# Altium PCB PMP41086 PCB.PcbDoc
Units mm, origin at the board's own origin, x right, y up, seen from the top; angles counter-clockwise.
Board outline 36.5 x 25.7 mm, 2 copper layers (Top Layer, Bottom Layer), stack 1.575 mm thick; 40 components, 22 nets, 87 pads, 45 vias.
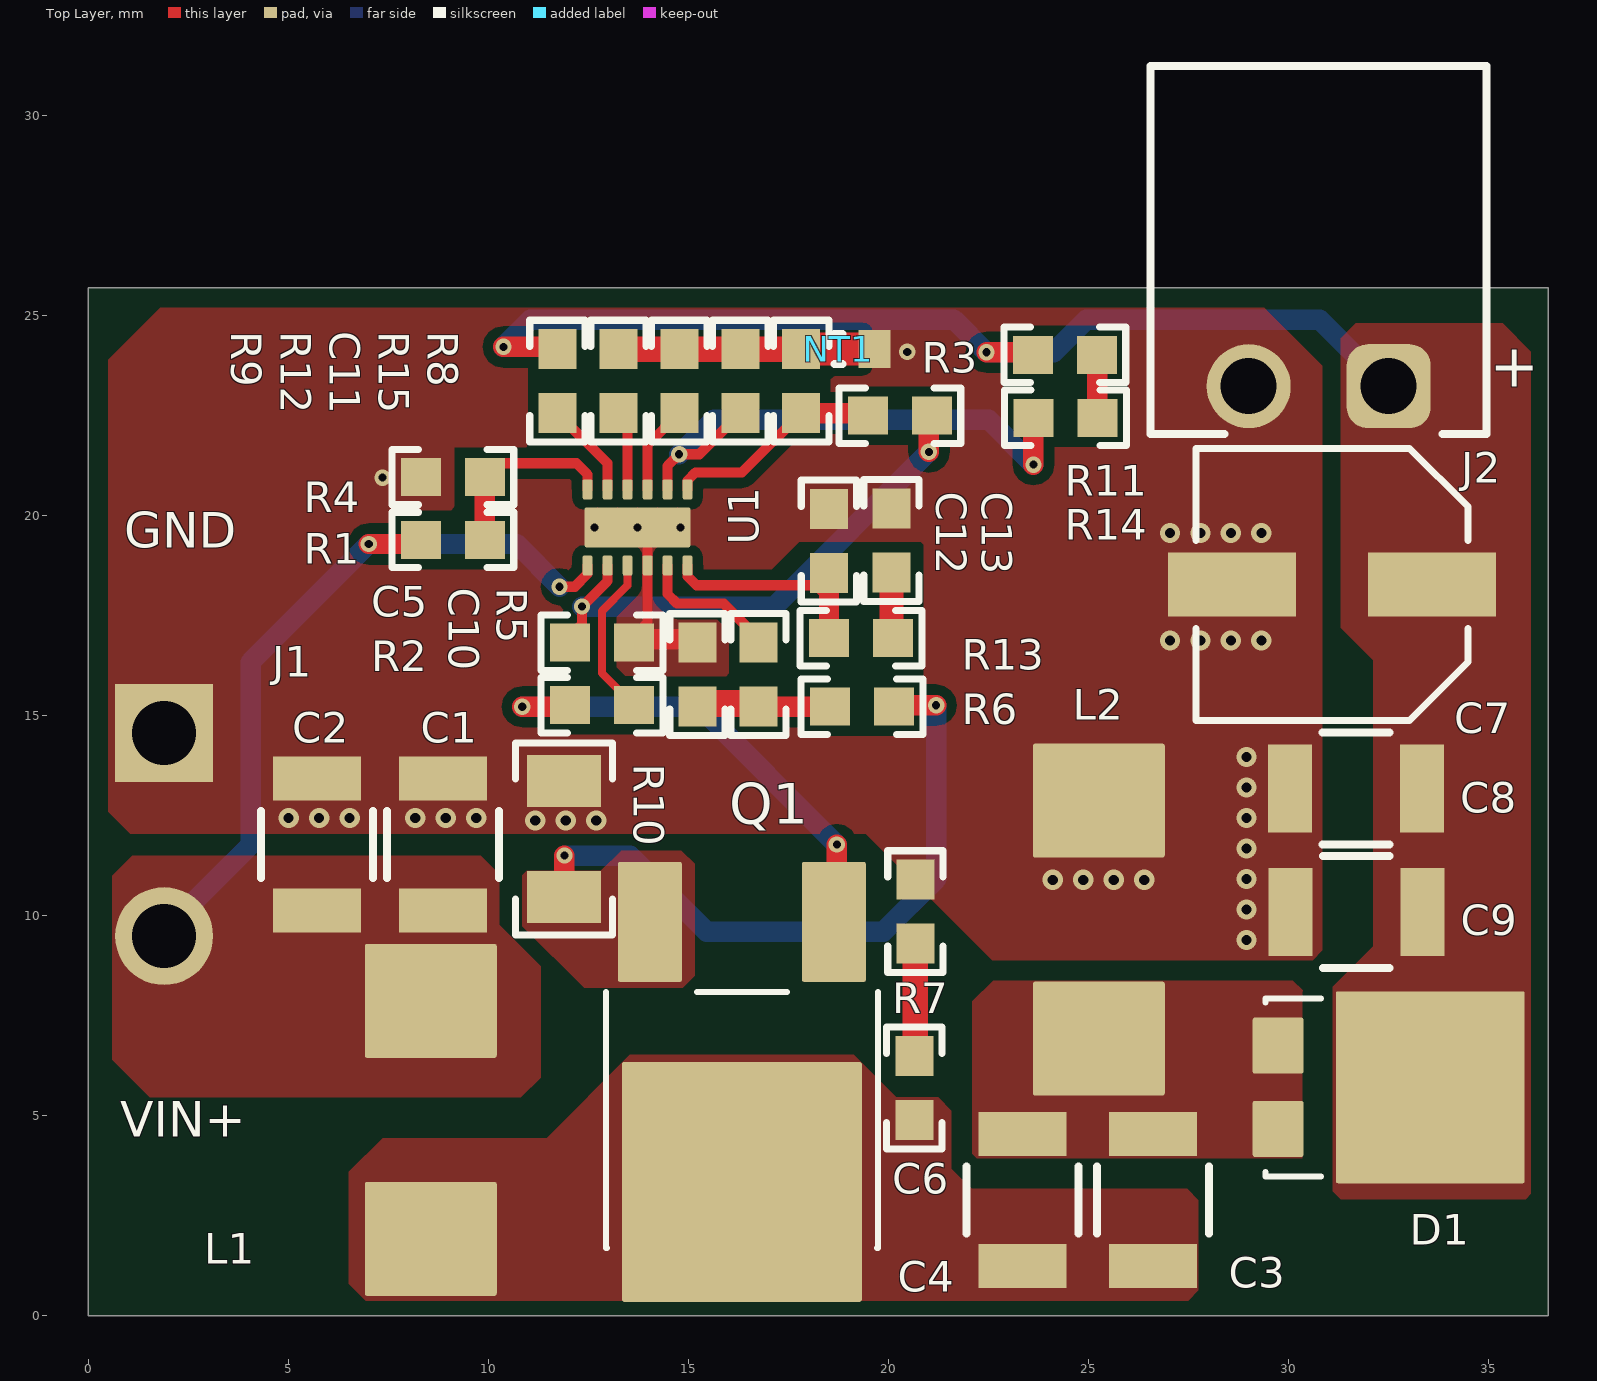
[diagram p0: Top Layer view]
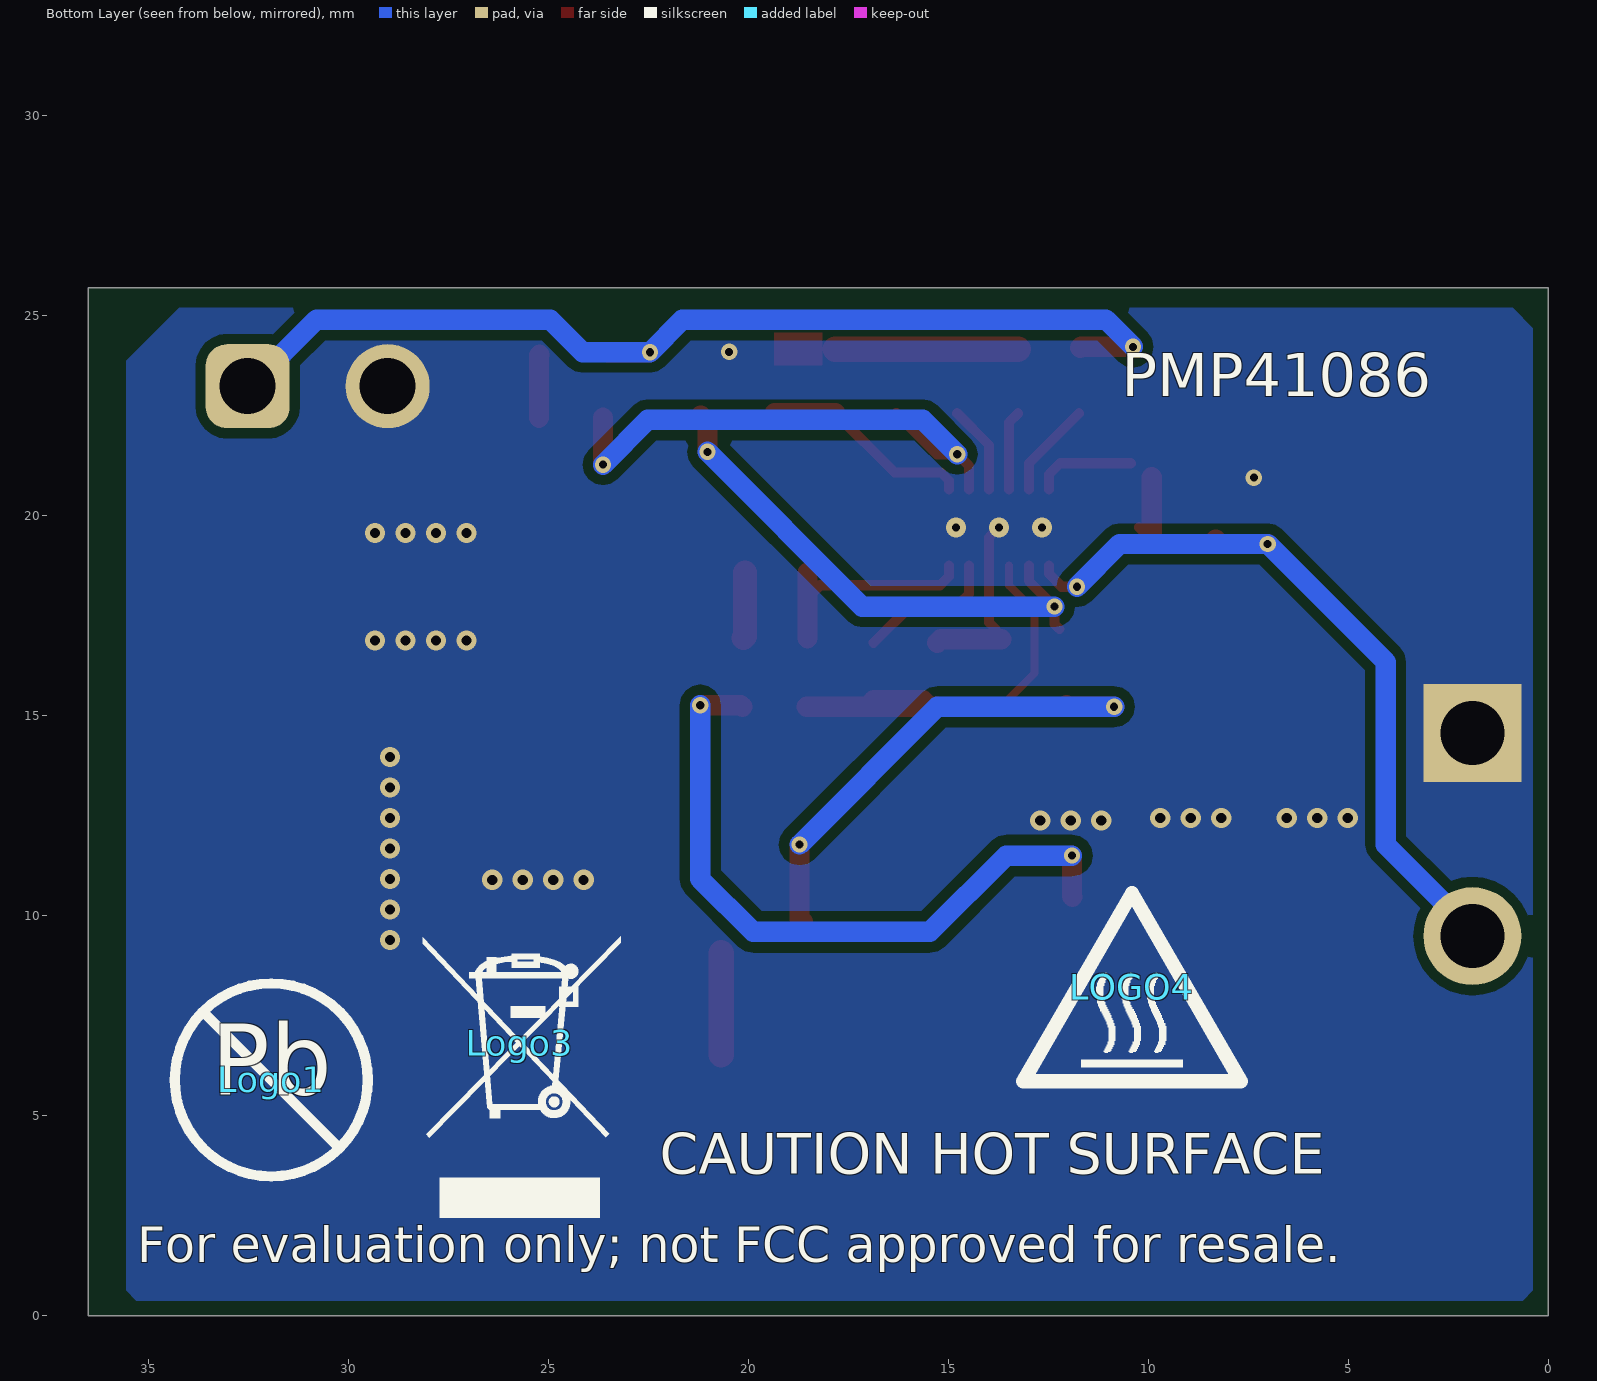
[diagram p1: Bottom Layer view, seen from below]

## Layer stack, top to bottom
Top Solder: solder mask 0.0102, Solder Resist, Dk 3.5
Top Layer: signal copper 0.0356
Dielectric1: core 1.5037, FR-4, Dk 4.8
Bottom Layer: signal copper 0.0356
Bottom Solder: solder mask 0.0102, Solder Resist, Dk 3.5

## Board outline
0,0 36.5,0 36.5,25.7 0,25.7

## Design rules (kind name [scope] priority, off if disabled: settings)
AcuteAngle [All] p1: minimum=4.50000000000000E+0001 checktracksonly=FALSE
AssemblyTestPointUsage [All] p1: valid=2
Clearance Clearance_BoardEdge_MountingHoles [OnCopper and InComponentClass('Mounting Holes') vs IsKeepOut] p1: gap=1.016 ignorepadtopadclearanceinfootprint=FALSE except(0: Arc-Hole Track-Hole SMDPad-Hole THPad-Hole Via-Hole Fill-Hole Poly-Hole Region-Hole Text-Hole)
Clearance Clearance_BoardEdge_Poly [OnCopper and InPoly vs IsKeepOut] p2: gap=0.635 ignorepadtopadclearanceinfootprint=FALSE except(0: Arc-Hole Track-Hole SMDPad-Hole THPad-Hole Via-Hole Fill-Hole Poly-Hole Region-Hole Text-Hole)
Clearance Clearance_BoardEdge [OnCopper and Not InComponentClass('Logo') and not InComponentClass('FiducialMark') and not InRegion(1000,500,4000,800) and Not IsKeepout vs IsKeepOut] p3: gap=0.127 ignorepadtopadclearanceinfootprint=FALSE except(0: Arc-Hole Track-Hole SMDPad-Hole THPad-Hole Via-Hole Fill-Hole Poly-Hole Region-Hole Text-Hole)
Clearance Clearance_Poly [InPolygon] p4: gap=0.254 ignorepadtopadclearanceinfootprint=FALSE
Clearance [All] p5: gap=0.2 ignorepadtopadclearanceinfootprint=FALSE
ComponentClearance ComponentClearance_Logo [All] p1: gap=0.254 collisioncheckmode=3 verticalgap=0.254 showdistances=TRUE
ComponentClearance ComponentClearance_ScrewToNut [(HasFootprint('NY PMS 440 0025 PH')) vs (HasFootprint('Keystone_1902C'))] p2: gap=0.127 collisioncheckmode=3 verticalgap=0.254 showdistances=FALSE
ComponentClearance ComponentClearance_MountingHoles [InComponentClass('Mounting Holes')] p3: gap=0.254 collisioncheckmode=3 verticalgap=2540 showdistances=FALSE
ComponentClearance ComponentClearance_SmallPassives [HasFootprint('0201*') or HasFootprint('0402*') or HasFootprint('0508') or HasFootprint('0603*') or HasFootprint('0612') or HasFootprint('0805*') or HasFootprint('0815*') or HasFootprint('0830*') or HasFootprint('1206*') or HasFootprint('1210*') or HasFootprint('1808*') or HasFootprint('1812*') or HasFootprint('1825*') or HasFootprint('2010*') or HasFootprint('2220*') or HasFootprint('2225*') or HasFootprint('2512*') or HasFootprint('2728*') or HasFootprint('3518*') vs HasFootprint('0201*') or HasFootprint('0402*') or HasFootprint('0508') or HasFootprint('0603*') or HasFootprint('0612') or HasFootprint('0805*') or HasFootprint('0815*') or HasFootprint('0830*') or HasFootprint('1206*') or HasFootprint('1210*') or HasFootprint('1808*') or HasFootprint('1812*') or HasFootprint('1825*') or HasFootprint('2010*') or HasFootprint('2220*') or HasFootprint('2225*') or HasFootprint('2512*') or HasFootprint('2728*') or HasFootprint('3518*')] p4: gap=0.254 collisioncheckmode=3 verticalgap=0.254 showdistances=FALSE
ComponentClearance ComponentClearance_THtoSMT [IsThruComponent vs IsSMTComponent] p5: gap=0.254 collisioncheckmode=3 verticalgap=2540 showdistances=FALSE
ComponentClearance ComponentClearance_THtoTH [IsThruComponent vs IsThruComponent] p6: gap=0.254 collisioncheckmode=3 verticalgap=2540 showdistances=FALSE
ComponentClearance [All] p7: gap=0.254 collisioncheckmode=3 verticalgap=0.254 showdistances=FALSE
DiffPairsRouting [All] p1: maxlimit=2.54 minlimit=0.254 mostfreqgap=0.254 toplayer_minwidth=0.381 toplayer_maxwidth=0.381 toplayer_prefwidth=0.381 bottomlayer_minwidth=0.381 bottomlayer_maxwidth=0.381 bottomlayer_prefwidth=0.381 maxuncoupledlength=25.4
FabricationTestPointUsage TestPointUsage [All] p1: valid=2 allowmultiple=FALSE
FabricationTestpoint Testpoint [All] p1: side=3 testpointundercomponent=TRUE minsize=1.016 maxsize=2.54 preferedsize=1.524 minholesize=0 maxholesize=1.016 preferedholesize=0.813 testpointgrid=0.025 allowsidetop=TRUE allowsidebottom=TRUE usegrid=TRUE gridtolerance=0
FanoutControl Fanout_LCC [IsLCC] p1: bgadir=Out bgaviamode=Centered fanoutstyle=Auto fanoutdirection=Alternating viagrid=0.025 // Fanout_LCC (Default Rule)
FanoutControl Fanout_BGA [IsBGA] p2: bgadir=Out bgaviamode=Centered fanoutstyle=Auto fanoutdirection=Alternating viagrid=0.025 // Fanout_BGA (Default Rule)
FanoutControl Fanout_Default [All] p4: bgadir=Out bgaviamode=Centered fanoutstyle=Auto fanoutdirection=Alternating viagrid=0.025 // Fanout_Default (Default Rule)
FanoutControl Fanout_Small [(CompPinCount < 5)] p5: bgadir=Out bgaviamode=Centered fanoutstyle=Auto fanoutdirection=OutThenIn viagrid=0.025 // Fanout_Small (Default Rule)
HoleSize [All] p1: absolutevalues=TRUE maxlimit=6.375 minlimit=0.152 maxpercent=80.000 minpercent=20.000
MinimumAnnularRing [All] p1: minimumring=0.076
MinimumSolderMaskSliver MinimumSolderMaskSliver_Logo [InComponentClass('Logo') vs InComponentClass('Logo')] p1: minsoldermaskwidth=0.018
MinimumSolderMaskSliver [All] p2: minsoldermaskwidth=0
PlaneConnect [All] p1: planeconnectstyle=Direct reliefexpansion=0.254 reliefentries=4 reliefconductorwidth=0.254 reliefairgap=0.254
PolygonConnect [All] p1: connectstyle=Direct reliefconductorwidth=0.254 reliefentries=4 polygonreliefangle="90 Angle" airgapwidth=0.254
RoutingCorners [All] p1: cornerstyle=45-Degree minsetback=0.254 maxsetback=2.54
RoutingVias [All] p1: holewidth=0.406 width=0.864 viastyle="Through Hole" minholewidth=0.198 minwidth=0.406 maxholewidth=1.016 maxwidth=1.651
SMDToCorner [All] p1: distance=0
SilkToBoardRegionClearance [Not ((IsComment or IsDesignator) And (Hide <> 'False')) and not InRegion(1000,500,4000,800)] p1:
SilkToSilkClearance [All] p1: silktosilkclearance=0
SilkToSolderMaskClearance SilkscreenOverComponentPads [IsPad] p1: minsilkscreentomaskgap=0 clearancetoexposedcopper=TRUE
SolderMaskExpansion [All] p1: expansion=0.076
Width [All] p1: maxlimit=2.54 minlimit=0.152 preferedwidth=0.254 checkconnectedcopper=TRUE
14 further rules are at their usual default settings.

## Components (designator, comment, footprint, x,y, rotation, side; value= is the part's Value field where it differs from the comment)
C1 "UMK325AB7106KMHT" 1210_280 8.875,11.784 r90 top value=10uF
C2 "UMK325AB7106KMHT" 1210_280 5.725,11.78 r90 top value=10uF
C3 "CGA6P3X7R1H475K250AB" 1210_280 26.616,2.9 r270 top value=4.7uF
C4 "CGA6P3X7R1H475K250AB" 1210_280 23.36,2.896 r270 top value=4.7uF
C5 "GCM188R71E105KA64D" 0603 12.842,16.828 r180 top value=1uF
C6 "GCM1885C2A221JA16D" 0603 20.653,5.698 r90 top value=220pF
C7 "EEE-FK1V101XP" SM_RADIAL_D8 31.094,18.288 r180 top value=100uF
C8 "UMK325AB7106KMHT" 1210_280 31.691,13.184 r180 top value=10uF
C9 "UMK325AB7106KMHT" 1210_280 31.702,10.092 r180 top value=10uF
C10 "CGA3E2NP01H101J080AA" 0603 15.23,16.028 r90 top value=100pF
C11 "CGA3E2X7R1E104K080AA" 0603 14.777,23.367 r90 top value=0.1uF
C12 "06035A221JAT2A" 0603 18.518,19.374 r90 top value=220pF
C13 "GCM188R71E473KA37D" 0603 20.08,19.381 r90 top value=0.047uF
D1 "RBQ10RSM65BTFTL1" FP-STPS1045SF_PSMC-MFG 32.512,5.715 r270 top
J1 "691313510002" FP-691313510002_TRM_BLK_HDR2-MFG -2.103,12.034 r270 top
J2 "691322110002" 691322110002 30.762,26.641 r180 top
L1 "SPM7054VC-220M-D" "FP-SPM7054VT- 470M-D_STM_7MM5_7MM0-0" 8.563,4.9 r90 top
L2 "SPM7054VC-220M-D" "FP-SPM7054VT- 470M-D_STM_7MM5_7MM0-0" 25.265,9.906 r270 top
Logo1 "Pb-Free Symbol" Pb-Free_Overlay_Medium 31.923,5.9 r180 bottom
Logo2 "FCC disclaimer" FCC_disclaimer 19.357,-5.7 r180 bottom
Logo3 "WEEE logo" WEEE_Minimum 25.716,6.833 r180 bottom
LOGO4 "CAUTION HOT SURFACE" IEC_HotSurface_Small 10.406,8.226 r180 bottom
NT1 "Net-Tie" NetTie_0603 18.755,24.167 r0 top net-tie
Q1 "RD3L150SNFRA" FP-RD3P08BBD_TO252-MFG 16.341,4.9 r180 top
R1 "RC0603FR-0768KL" 0603 9.113,19.4 r180 top value=68.0k
R2 "RC0603JR-070RL" 0603 12.842,15.266 r180 top value=0
R3 "ERJ-3GEY0R00V" 0603 20.288,22.504 r0 top value=0
R4 "CRCW060325K5FKEA" 0603 9.113,20.969 r0 top value=25.5k
R5 "ERJ-3GEY0R00V" 0603 16.754,16.033 r270 top value=0
R6 "CRCW0603100RFKEA" 0603 19.343,15.228 r0 top value=100
R7 "CRCW060310R0JNEA" 0603 20.679,10.104 r270 top value=10
R8 "ERJ-3GEY0R00V" 0603 17.825,23.367 r90 top value=0
R9 "CRCW0603100KFKEA" 0603 11.729,23.367 r270 top value=100k
R10 "CSR1206FK25L0" 1206 11.894,11.926 r270 top value=0.025
R11 "CRCW060349R9FKEA" 0603 24.416,24.027 r180 top value=49.9
R12 "CRCW06039K09FKEA" 0603 13.253,23.367 r270 top value=9.09k
R13 "CRCW06033K92FKEA" 0603 19.318,16.944 r180 top value=3.92k
R14 "CRCW0603100KFKEA" 0603 24.43,22.452 r0 top value=100k
R15 "CRCW06034K99FKEA" 0603 16.301,23.367 r270 top value=4.99k
U1 "LM5156QDSSRQ1" DSS0012C 13.732,19.711 r90 top

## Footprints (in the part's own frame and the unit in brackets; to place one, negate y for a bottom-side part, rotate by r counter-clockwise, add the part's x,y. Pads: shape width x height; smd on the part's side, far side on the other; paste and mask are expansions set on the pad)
0603 [mm] "0603 from SM-752 data"
  rect 1x0.95 smd: 1(-0.8,0) 2(0.8,0)
  silkscreen extent -1.52,-0.69 1.52,0.69, body extent -0.87,-0.47 0.87,0.47, height 1
1206 [mm] "1206 from SM-752 data"
  rect 1.3x1.85 smd: 1(-1.45,0) 2(1.45,0)
  silkscreen extent -2.4,-1.21 2.4,1.21, body extent -1.7,-0.9 1.7,0.9, height 1.35
1210_280 [mm] "SMD, 2-Leads, Body 3.6x2.8mm, Height 2.8mm"
  rect 1.1x2.2 smd: 1(-1.65,0) 2(1.65,0)
  silkscreen extent -0.84,-1.4 0.84,1.4, body extent -1.8,-1.4 1.8,1.4, height 2.8
691322110002 [mm] "Horizontal PCB Header, pitch 3.5mm, 02p"
  rrect50% 2.1x2.1 hole 1.4: 1(-1.75,3.4)
  round 2.1 hole 1.4: 2(1.75,3.4)
  silkscreen extent -4.2,-4.6 4.2,4.6, body extent -4.2,-4.6 4.2,4.6, height 7.3
DSS0012C [mm] "WSON-12"
  rrect40% 0.5x0.25 smd: 1(-0.95,1.25) 2(-0.95,0.75) 3(-0.95,0.25) 4(-0.95,-0.25) 5(-0.95,-0.75) 6(-0.95,-1.25) 7(0.95,-1.25) 8(0.95,-0.75) 9(0.95,-0.25) 10(0.95,0.25) 11(0.95,0.75) 12(0.95,1.25)
  rrect11% 0.95x1.17 on Top Paste: 13(0,0.685) 13(0,-0.685)
  rrect11% 1x2.65 smd paste-0.5: 13(0,0)
  body extent -1,-1.5 1,1.5, height 0.81
FCC_disclaimer [mm]
FP-691313510002_TRM_BLK_HDR2-MFG [mm]
  rect 2.45x2.45 hole 1.6 paste-1000 mask+0: 1(-2.54,4)
  round 2.45 hole 1.6 paste-1000 mask+0: 2(2.54,4)
  body extent -6.25,-6.2 6.25,6.2, height 0.25
FP-RD3P08BBD_TO252-MFG [mm]
  rrect6% 1.6x3 smd paste+0 mask+0: 1(-2.3,-4.95) 3(2.3,-4.95)
  rrect2% 6x6 smd paste+0 mask+0: 4(0,1.55)
  silkscreen extent -3.4,-3.2 3.4,3.2, body extent -3.5,-6.55 3.5,4.65, height 0.25
"FP-SPM7054VT- 470M-D_STM_7MM5_7MM0-0" [mm]
  rrect4% 2.85x3.3 smd paste+0 mask+0: 1(-2.975,0) 2(2.975,0)
  body extent -4.5,-3.8 4.5,3.8, height 0.25
FP-STPS1045SF_PSMC-MFG [mm]
  rrect2% 4.8x4.72 smd paste+0 mask+0: 1(0,1.04)
  rrect8% 1.4x1.27 smd paste+0 mask+0: 2(-1.04,-2.765) 3(1.04,-2.765)
  silkscreen extent -2.22,-3.08 2.22,-1.7, body extent -2.5,-3.5 2.5,3.5, height 0.25
IEC_HotSurface_Small [mm]
  silkscreen extent -2.72,-2.36 2.72,2.35
NetTie_0603 [mm] "Net Tie 0603 size"
  rect 0.8x0.95 smd paste-1: 1(-0.9,0) 2(0.9,0)
  Top Layer region: -0.6,0.406 0.6,0.406 0.6,-0.406 -0.6,-0.406
  silkscreen extent -0.1,-0.38 0.1,0.38
Pb-Free_Overlay_Medium [mm]
  silkscreen extent -2.41,-2.41 2.41,2.41
SM_RADIAL_D8 [mm] "6.3 x 7.7mm:  Panasonic D8"
  rect 3.2x1.6 smd: 1(-2.5,0) 2(2.5,0)
  silkscreen extent -3.4,-3.4 3.4,3.4, body extent -3.4,-3.4 3.4,3.4, height 8.01
WEEE_Minimum [mm] "WEEElie bin"
  silkscreen extent -2.42,-4.38 2.52,2.65

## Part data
C1 C2 C8 C9: library part CMP-0009258-1, "CAP, CERM, 10 uF, 50 V, +/- 10%, X7R, AEC-Q200 Grade 1, 1210", Cap_Case=1210, Manufacturer="Taiyo Yuden", Supplier Part Number 1=587-4326-1-ND, TempCo=X7R, Tolerance_%=10%, Value1=Unknown, Value2=50V, ValueDisplayed=10uF
C3 C4: library part CMP-0009162-1, "CAP, CERM, 4.7 uF, 50 V, +/- 10%, X7R, AEC-Q200 Grade 1, 1210", Cap_Case=1210_280, Manufacturer=TDK, Supplier Part Number 1=445-6999-1-ND, TempCo=X7R, Tolerance_%=10%, Value1="0.003166 ohm", Value2=50V, ValueDisplayed=4.7uF
C5: library part CMP-0007139-4, "CAP, CERM, 1 uF, 25 V, +/- 10%, X7R, AEC-Q200 Grade 1, 0603", Cap_Case=0603, Manufacturer=MuRata, Supplier Part Number 1=490-10673-1-ND, TempCo=X7R, Tolerance_%=10%, Value1=Unknown, Value2=25V, ValueDisplayed=1uF
C6: library part CMP-0860912-1, "CAP, CERM, 220 pF, 100 V,+/- 5%, C0G/NP0, AEC-Q200 Grade 1, 0603", Cap_Case=0603, Manufacturer=MuRata, TempCo=C0G/NP0, Tolerance_%=5%, Value2=100V, ValueDisplayed=220pF
C7: library part CMP-0010724-1, "CAP, AL, 100 uF, 35 V, +/- 20%, 0.34 ohm, AEC-Q200 Grade 2, SMD", Cap_Case=D8, Manufacturer=Panasonic, Supplier Part Number 1=PCE3836CT-ND, Tolerance_%=20%, Value1="0.34 ohm", Value2=35V, ValueDisplayed=100uF
C10: library part CMP-0007075-1, "CAP, CERM, 100 pF, 50 V, +/- 5%, C0G/NP0, AEC-Q200 Grade 0, 0603", Cap_Case=0603, Manufacturer=TDK, Supplier Part Number 1=445-12386-1-ND, TempCo=C0G/NP0, Tolerance_%=5%, Value1=Unknown, Value2=50V, ValueDisplayed=100pF
C11: library part CMP-0007077-3, "CAP, CERM, 0.1 uF, 25 V, +/- 10%, X7R, AEC-Q200 Grade 1, 0603", Cap_Case=0603, Manufacturer=TDK, Supplier Part Number 1=445-5667-1-ND, TempCo=X7R, Tolerance_%=10%, Value1=Unknown, Value2=25V, ValueDisplayed=0.1uF
C12: library part CMP-0006777-1, "CAP, CERM, 220 pF, 50 V, +/- 5%, C0G/NP0, 0603", Cap_Case=0603, Manufacturer=AVX, Supplier Part Number 1=478-1179-1-ND, TempCo=C0G/NP0, Tolerance_%=5%, Value1="0.083 ohm", Value2=50V, ValueDisplayed=220pF
C13: library part CMP-0007141-5, "CAP, CERM, 0.047 uF, 25 V, +/- 10%, X7R, AEC-Q200 Grade 1, 0603", Cap_Case=0603, Manufacturer=MuRata, Supplier Part Number 1=490-8018-1-ND, TempCo=X7R, Tolerance_%=10%, Value1=Unknown, Value2=25V, ValueDisplayed=0.047uF
D1: library part CMP-0098014-1, "DIODE SCHOTTKY 65V 10A TO277A", Forward Current=10A, Manufacturer=Rohm
J1: library part CMP-0074821-1, "TERM BLK HDR 5.08MM HORZ PCB 2P", Current_A=20A, Manufacturer="Wurth Electronics", Voltage_V=300V
J2: "WR-TBL Serie 3221 Horizontal PCB Header, Pluggable, THT, pitch 3.5mm, 2p", Manufacturer="Wurth Elektronik", Operating Temperature="-40 to +105degC", Rated Current [UL]=10A, Working Voltage [UL]=300VAC
L1 L2: library part CMP-0088010-1, "FIXED IND 22UH 4A 0.0652OHM SMD", Manufacturer=TDK
Logo1: library part CMP-0074839-1
Logo2: library part CMP-0074847-1, "FCC_disclaimer"
Logo3: library part CMP-0074769-1
LOGO4: library part CMP-0074837-1, "IEC 61010-1 Hot Surface Warning"
NT1: "Single point connection between nets."
Q1: library part CMP-0093637-1, "N-Channel 80A (Ta) 119W (Ta) Surface Mount TO-252", Input Capacitace At Vds="1940pF @ 50V", Manufacturer=Rohm, Mouser Part Number=755-RD3P08BBDTL, Operating Temperature Range="-55°C to +150°C"
R1: library part CMP-0023239-1, "RES, 68.0 k, 1%, 0.1 W, 0603", Manufacturer="Yageo America", Power_W=100mW, Supplier Part Number 1=311-68.0KHRCT-ND, TempCo="200 ppm/C", Tolerance_%=1%, Value2=0.1W, Value_Code=68k0, ValueDisplayed=68.0k
R2: library part CMP-0025885-5, "RES, 0, 5%, 0.1 W, 0603", Manufacturer=Yageo, Power_W=100mW, Supplier Part Number 1=311-0.0GRCT-ND, TempCo="200 ppm/C", Tolerance_%=5%, Value2=0.1W, Value_Code=0000, ValueDisplayed=0
R3 R5 R8: library part CMP-0025874-4, "RES, 0, 5%, 0.1 W, AEC-Q200 Grade 0, 0603", Manufacturer=Panasonic, Power_W=100mW, Supplier Part Number 1=P0.0GCT-ND, TempCo="600 ppm/C", Tolerance_%=5%, Value2=0.1W, Value_Code=0000, ValueDisplayed=0
R4: library part CMP-0022242-4, "RES, 25.5 k, 1%, 0.1 W, AEC-Q200 Grade 0, 0603", Manufacturer=Vishay-Dale, Power_W=100mW, Supplier Part Number 1=541-25.5KHCT-ND, TempCo="100 ppm/C", Tolerance_%=1%, Value2=0.1W, Value_Code=25k5, ValueDisplayed=25.5k
R6: library part CMP-0021991-4, "RES, 100, 1%, 0.1 W, AEC-Q200 Grade 0, 0603", Manufacturer=Vishay-Dale, Power_W=100mW, Supplier Part Number 1=541-100HCT-ND, TempCo="100 ppm/C", Tolerance_%=1%, Value2=0.1W, Value_Code=100R, ValueDisplayed=100
R7: library part CMP-0025703-4, "RES, 10, 5%, 0.1 W, AEC-Q200 Grade 0, 0603", Manufacturer=Vishay-Dale, Power_W=100mW, Supplier Part Number 1=541-10GCT-ND, TempCo="200 ppm/C", Tolerance_%=5%, Value2=0.1W, Value_Code=10R0, ValueDisplayed=10
R9 R14: library part CMP-0021990-4, "RES, 100 k, 1%, 0.1 W, AEC-Q200 Grade 0, 0603", Manufacturer=Vishay-Dale, Power_W=100mW, Supplier Part Number 1=541-100KHCT-ND, TempCo="100 ppm/C", Tolerance_%=1%, Value2=0.1W, Value_Code=100k
R10: library part CMP-0017261-1, "RES, 0.025, 1%, 0.5 W, 1206", Manufacturer="Stackpole Electronics Inc", Power_W=500mW, Supplier Part Number 1=CSR1206FK25L0CT-ND, TempCo="100 ppm/C", Tolerance_%=1%, Value2=0.5W, Value_Code=R025, ValueDisplayed=0.025
R11: library part CMP-0022448-4, "RES, 49.9, 1%, 0.1 W, AEC-Q200 Grade 0, 0603", Manufacturer=Vishay-Dale, Power_W=100mW, Supplier Part Number 1=541-49.9HCT-ND, TempCo="100 ppm/C", Tolerance_%=1%, Value2=0.1W, Value_Code=49R9, ValueDisplayed=49.9
R12: library part CMP-0022665-4, "RES, 9.09 k, 1%, 0.1 W, AEC-Q200 Grade 0, 0603", Manufacturer=Vishay-Dale, Power_W=100mW, Supplier Part Number 1=541-9.09KHCT-ND, TempCo="100 ppm/C", Tolerance_%=1%, Value2=0.1W, Value_Code=9k09, ValueDisplayed=9.09k
R13: library part CMP-0022383-4, "RES, 3.92 k, 1%, 0.1 W, AEC-Q200 Grade 0, 0603", Manufacturer=Vishay-Dale, Power_W=100mW, Supplier Part Number 1=541-3.92KHCT-ND, TempCo="100 ppm/C", Tolerance_%=1%, Value2=0.1W, Value_Code=3k92, ValueDisplayed=3.92k
R15: library part CMP-0022458-4, "RES, 4.99 k, 1%, 0.1 W, AEC-Q200 Grade 0, 0603", Manufacturer=Vishay-Dale, Power_W=100mW, Supplier Part Number 1=541-4.99KHCT-ND, TempCo="100 ppm/C", Tolerance_%=1%, Value2=0.1W, Value_Code=4k99, ValueDisplayed=4.99k
U1: library part CMP-0860751-1, "2.2-MHz Wide VIN 65-V Non-synchronous Boost/SEPIC/Flyback Controller with Dual Random Spread Spectrum, DSS0012C (WSON-12)", Alternate Manufacturer="Texas Instruments", Alternate PartNumber=LM5156QDSSTQ1

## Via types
v1: diameter 0.508, hole 0.254, Top Layer to Bottom Layer, 28 vias
v2: diameter 0.406, hole 0.203, Top Layer to Bottom Layer, 14 vias
v3: diameter 0.5, hole 0.2, Top Layer to Bottom Layer, 3 vias

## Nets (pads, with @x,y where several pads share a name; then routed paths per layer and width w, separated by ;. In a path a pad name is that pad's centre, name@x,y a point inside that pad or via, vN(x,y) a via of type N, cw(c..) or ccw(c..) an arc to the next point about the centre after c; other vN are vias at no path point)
AGND: C11.2 NT1.1 R8.2 R12.1 R15.1 | length 4.6
  Top Layer w0.635: R12.1 C11.2 R8.2
GND: C1.2 C2.2 C5.1 C7.2 C8.2 C9.2 C10.2 C12.2 C13.2 J1.1 J2.2 L2.1 NT1.2 R4.1 R7.1 R10.1 U1.4 U1.13@13.732,19.711 | length 4.3
  Top Layer w0.254: v3(13.732,19.711) 13.982,19.461 U1.4 13.982,17.333 C5.1@13.82,17.171
  Top Layer w0.508: C5.1@13.676,16.917 15.185,16.917 C10.2@15.274,16.828
  other v1: 28.955,9.398 28.955,10.16 24.114,10.9 24.876,10.9 25.638,10.9 26.4,10.9 28.955,10.922 28.955,11.684 11.176,12.382 11.938,12.382 12.7,12.382 5.011,12.446 5.773,12.446 6.535,12.446 8.176,12.446 8.938,12.446 9.7,12.446 28.955,12.446 28.955,13.208 28.955,13.97 27.043,16.884 27.805,16.884 28.567,16.884 29.329,16.884 27.043,19.572 27.805,19.572 28.567,19.572 29.329,19.572
  other v2: 7.359,20.955 20.477,24.1
  other v3: 12.657,19.711 14.807,19.711
NetC3_1: C3.1 C4.1 D1.2 D1.3 L2.2
NetC3_2: C3.2 C4.2 C6.1 L1.1 Q1.4
NetC6_2: C6.2 R7.2 | length 2.6
  Top Layer w0.635: C6.2@20.679,6.524 R7.2@20.679,9.076
NetC10_1: C10.1 R5.2 R6.1 | length 4.9
  Top Layer w0.508: C10.1@15.274,15.228 C10.1@15.471,15.228 ; R5.2 16.759,15.228 R5.2@16.868,15.228 ; R5.2@16.881,15.381 16.868,15.393 15.636,15.393 C10.1@15.471,15.228 ; R6.1 R5.2@16.868,15.228 ; C10.1@15.471,15.228 R5.2@16.868,15.228
NetC11_1: C11.1 U1.9 | length 2.2
  Top Layer w0.254: U1.9 13.982,21.773 C11.1
NetC12_1: C12.1 R13.2 U1.6 | length 5.7
  Top Layer w0.254: U1.6 14.982,18.489 15.207,18.264 18.203,18.264 18.518,17.95
  Top Layer w0.508: R13.2 18.518,17.95 C12.1
NetC13_1: C13.1 R13.1 | length 1.7
  Top Layer w0.6: C13.1 20.08,16.982 R13.1
NetQ1_1: Q1.1 R2.2 | length 12.5
  Top Layer w0.508: v2(10.852,15.228) 12.004,15.228 R2.2 ; Q1.1 18.716,9.925 v2(18.716,11.784)
  Bottom Layer w0.508: v2(10.852,15.228) 15.271,15.228 v2(18.716,11.784)
NetQ1_3: Q1.3 R6.2 R10.2 | length 17.1
  Top Layer w0.508: R10.2 11.905,10.486 v2(11.905,11.506) ; R6.2 20.181,15.266 v2(21.199,15.266)
  Bottom Layer w0.508: v2(11.905,11.506) 13.552,11.506 15.458,9.6 19.879,9.6 21.199,10.92 v2(21.199,15.266)
NetR1_1: R1.1 R4.2 U1.12 | length 4.6
  Top Layer w0.254: R1.1 R1.1@10.227,19.714 ; 10.43,21.314 12.205,21.314 12.482,21.037 U1.12
  Top Layer w0.508: R1.1 R4.2
NetR2_1: R2.1 U1.3 | length 4.1
  Top Layer w0.2: U1.3 13.482,18.264 12.842,17.625 12.842,16.066 R2.1
NetR3_1: R3.1 R8.1 U1.7 | length 5.3
  Top Layer w0.254: U1.7 14.982,20.886 15.179,21.083 16.341,21.083 R8.1
  Top Layer w0.508: R8.1 19.343,22.567 R3.1@19.345,22.569
NetR5_1: R5.1 U1.5 | length 3.6
  Top Layer w0.254: U1.5 14.482,18.046 14.722,17.806 15.89,17.806 R5.1@16.868,16.828
NetR9_2: R9.2 U1.11 | length 2.4
  Top Layer w0.254: R9.2 12.982,21.314 U1.11
NetR11_1: R11.1 R14.2 | length 1.6
  Top Layer w0.508: R11.1 25.23,24.013 R14.2
NetR12_2: R12.2 U1.10 | length 2
  Top Layer w0.254: R12.2 13.482,22.338 U1.10
NetR14_1: R14.1 R15.2 U1.8 | length 13.8
  Top Layer w0.254: U1.8 14.482,21.25 v2(14.773,21.54) 15.274,21.54 R15.2
  Top Layer w0.508: v2(23.63,21.28) R14.1
  Bottom Layer w0.508: v2(14.773,21.54) 15.633,22.4 22.51,22.4 v2(23.63,21.28)
VCC: C5.2 R3.2 U1.2 | length 13.2
  Top Layer w0.254: C5.2@12.22,17.171 12.345,17.296 v2(12.345,17.731) 12.982,18.368 U1.2
  Top Layer w0.508: v2(21.016,21.6) 21.016,22.331 R3.2@21.189,22.504
  Bottom Layer w0.508: v2(12.345,17.731) 17.147,17.731 v2(21.016,21.6)
VIN: C1.1 C2.1 J1.2 L1.2 R1.2 U1.1 | length 19.5
  Top Layer w0.254: v2(11.781,18.229) 12.162,18.229 12.482,18.55 U1.1
  Top Layer w0.508: v2(7.013,19.298) 8.211,19.298 R1.2
  Bottom Layer w0.508: J1.2 1.897,9.614 4.064,11.781 4.064,16.349 v2(7.013,19.298) 10.712,19.298 v2(11.781,18.229)
VOUT: C7.1 C8.1 C9.1 D1.1 J2.1 R9.1 R11.2 | length 26.1
  Top Layer w0.508: v2(10.379,24.225) 11.671,24.225 R9.1@11.696,24.2 ; v2(22.455,24.09) R11.2@23.504,24.09
  Bottom Layer w0.508: v2(10.379,24.225) 11.054,24.9 21.646,24.9 v2(22.455,24.09) 24.142,24.09 24.952,24.9 30.794,24.9 J2.1@32.448,23.246
pads on no net: U1.13@13.047,19.711 U1.13@14.417,19.711

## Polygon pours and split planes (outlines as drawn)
NetQ1_3 on Top Layer "TOP_LAYER_NETQ1_3_P022" (solid, remove dead copper, pour order 22): 10.852,11.012 10.965,11.125 12.819,11.125 13.327,11.628 14.83,11.628 15.158,11.3 15.158,8.5 14.857,8.2 12.396,8.2 10.852,9.744
GND on Top Layer "TOP_LAYER_GND_P018" (solid, remove dead copper, pour order 18): 1.05,12.05 0.5,12.6 0.5,23.9 1.8,25.2 29.402,25.2 30.853,23.749 30.853,9.135 30.608,8.89 22.598,8.89 19.438,12.05
VIN on Top Layer "TOP_LAYER_VIN_P014" (solid, remove dead copper, pour order 14): 1.539,5.461 0.6,6.4 0.6,11.006 1.1,11.506 1.106,11.5 3.416,11.5 9.816,11.5 10.275,11.041 10.275,9.777 11.312,8.74 11.312,5.957 10.816,5.461 4.31,5.461
VOUT on Top Layer "TOP_LAYER_VOUT_P012" (solid, remove dead copper, pour order 12): 31.266,8.382 31.115,8.231 31.115,3.116 31.31,2.921 35.941,2.921 36.068,3.048 36.068,24.108 35.36,24.816 31.691,24.816 31.31,24.435 31.31,17.2 32.123,16.387 32.123,9.239
NetC3_1 on Top Layer "TOP_LAYER_NETC3_1_P010" (solid, remove dead copper, pour order 10): 30.4,3.988 30.349,3.937 22.217,3.937 22.101,4.053 22.101,7.859 22.623,8.382 30.118,8.382 30.4,8.1
NetC3_2 on Top Layer "TOP_LAYER_NETC3_2_P008" (solid, remove dead copper, pour order 8): 11.459,4.443 13.54,6.524 19.137,6.524 20.2,5.461 21.251,5.461 21.582,5.13 21.582,3.683 22.09,3.175 27.475,3.175 27.754,2.896 27.754,0.635 27.5,0.381 6.935,0.381 6.516,0.8 6.516,3.6 7.359,4.443
GND on Bottom Layer "BOTTOM_LAYER_GND_P020" (solid, remove dead copper, pour order 20): 0.635,0.381 0.381,0.635 0.381,24.692 0.889,25.2 34.228,25.2 35.552,23.876 35.552,0.635 35.298,0.381

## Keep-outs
Keep-Out Layer:
  text ".Layer_Name" at 14.656,-21.806 h1.52

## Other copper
Top Layer:
  pour cut-out: 17.775,19.335 17.03,18.59 17.03,16.225 18.024,15.231 20.818,15.235 20.872,15.288 20.872,19.282 20.818,19.335
  text ".Layer_Name" at 14.656,-21.806 h1.52
Bottom Layer:
  text ".Layer_Name" at 14.656,-21.806 h1.52

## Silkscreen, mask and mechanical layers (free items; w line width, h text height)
Top Overlay:
  text "+" at 35.044,22.86 h1.85
  text "GND" at 0.9,18.899 h1.52
  text "VIN+" at 0.8,4.175 h1.52
  text ".Layer_Name" at 14.656,-21.806 h0.6
Bottom Overlay:
  text "PMP41086" at 10.66,22.625 h1.85
  text ".Layer_Name" at 14.656,-21.806 h0.6
Top Paste:
  text ".Layer_Name" at 14.656,-21.806 h1.52
Bottom Paste:
  text ".Layer_Name" at 14.656,-21.806 h1.52
Top Solder:
  text ".Layer_Name" at 14.656,-21.806 h1.52
  text ".Layer_Name" at 14.656,-21.806 h1.52
Bottom Solder:
  text ".Layer_Name" at 14.656,-21.806 h1.52
Drill Guide:
  text ".Layer_Name" at 14.656,-21.806 h1.52
M1 Board Outline:
  the board outline again, w0.254
  text ".Layer_Name" at 14.656,-21.806 h1.52
M2 Board Dimensions:
  text ".Layer_Name" at 14.656,-21.806 h1.52
M3 3D STEP Top:
  text ".Layer_Name" at 14.656,-21.806 h1.52
M4 3D STEP Bottom:
  text ".Layer_Name" at 14.656,-21.806 h1.52
M5 Assembly Top:
  lines w0.254: -7.417,-23.626 160.223,-23.626 ; -7.417,-18.462 160.274,-18.462 ; -7.417,-13.297 -7.417,-28.791 94.31,-28.791 160.274,-28.791 160.274,-13.297 -7.404,-13.297 -7.404,-28.791 32.614,-28.791 ; 55.194,-28.791 55.194,-13.297 ; 87.376,-18.462 87.376,-13.297 ; 108.712,-18.462 108.712,-13.297 ; 124.511,-28.956 124.511,-23.804
  text "COMPONENTS MARKED 'DNP' SHOULD NOT BE POPULATED." at 29.299,-8.09 h1.52
  text "ASSEMBLY VARIANT:" at 29.286,-11.024 h1.52
  text ".VariantName" at 55.601,-11.024 h1.52
  text "PCB VIEWED FROM TOP SIDE" at -5.804,-16.654 h1.52
  text "BOARD #:" at 57.099,-16.654 h1.52
  text ".PRJ_Number" at 70.955,-16.654 h1.52
  text "REV:" at 92.405,-16.654 h1.52
  text ".PCB_Rev" at 99.809,-16.654 h1.52
  text "SVN REV:" at 113.69,-16.654 h1.52
  text ".VersionControl_RevNumber" at 126.543,-16.654 h1.52
  text "TID #:" at 57.099,-21.819 h1.52
  text ".TID" at 70.955,-21.819 h1.52
  text "PLOT NAME =" at -5.804,-27.034 h1.52
  text ".plot_File_Name" at 14.656,-27.034 h1.52
  text "GENERATED    :" at 57.15,-27.034 h1.52
  text ".Print_Date" at 79.235,-27.034 h1.52
  text ".Print_Time" at 97.752,-27.034 h1.52
  text "TEXAS INSTRUMENTS" at 129.87,-27.034 h1.52
M6 Assembly Bottom:
  lines w0.254: -7.429,-18.474 160.261,-18.474 ; -7.379,-23.639 160.261,-23.639 ; 28.334,-28.969 28.334,-23.817 ; 44.133,-18.474 44.133,-13.31 ; 65.468,-18.474 65.468,-13.31 ; 97.65,-28.804 97.65,-13.31 ; 120.231,-28.804 160.249,-28.804 160.249,-13.31 -7.429,-13.31 -7.429,-28.804 58.534,-28.804 160.261,-28.804 160.261,-13.31
  text "COMPONENTS MARKED 'DNP' SHOULD NOT BE POPULATED." at 154.991,-8.077 h1.52
  text ".VariantName" at 128.473,-11.024 h1.52
  text "ASSEMBLY VARIANT:" at 154.864,-11.024 h1.52
  text ".VersionControl_RevNumber" at 26.302,-16.667 h1.52
  text "SVN REV:" at 39.154,-16.667 h1.52
  text ".PCB_Rev" at 53.035,-16.667 h1.52
  text "REV:" at 60.439,-16.667 h1.52
  text ".PRJ_Number" at 81.89,-16.667 h1.52
  text "BOARD #:" at 95.745,-16.667 h1.52
  text "PCB VIEWED FROM BOTTOM SIDE" at 158.648,-16.667 h1.52
  text ".TID" at 81.89,-21.831 h1.52
  text "TID #:" at 95.745,-21.831 h1.52
  text "TEXAS INSTRUMENTS" at 22.974,-27.047 h1.52
  text ".Print_Time" at 55.093,-27.047 h1.52
  text ".Print_Date" at 73.609,-27.047 h1.52
  text "GENERATED    :" at 95.694,-27.047 h1.52
  text ".plot_File_Name" at 138.189,-27.047 h1.52
  text "PLOT NAME =" at 158.648,-27.047 h1.52
M9 Title Sheet:
  drawing of 57 lines, arcs and shapes, not listed
  text "1" at 18.792,204.127 h1.78
  text "2" at 82.182,204.127 h1.78
  text "3" at 145.411,204.127 h1.78
  text "4" at 209.08,204.127 h1.78
  text "5" at 272.555,204.127 h1.78
  text "6" at 336.182,204.127 h1.78
  text "A" at -10.579,175.095 h1.78
  text "A" at 365.341,175.095 h1.78
  text "B" at -10.579,114.643 h1.78
  text "B" at 365.341,114.643 h1.78
  text "C" at -10.579,54.318 h1.78
  text "C" at 365.341,54.318 h1.78
  text "PROJECT TITLE:" at 288.125,7.048 h1.14
  text ".PRJ_Title" at 289.395,3.662 h1.78
  text "DESIGNED FOR:" at 288.125,-0.597 h1.14
  text ".PRJ_Customer" at 289.395,-4.153 h1.78
  text "D" at -10.579,-5.88 h1.78
  text "D" at 365.341,-5.88 h1.78
  text "FILE NAME:" at 288.125,-8.217 h1.14
  text ".PCB_File_Name_No_Path" at 289.395,-11.265 h1.78
  text "Texas Instruments (TI) and/or its licensors do not warrant the accuracy or completeness of this specification" at 161.9,-15.376 h1.14
  text "ENGINEER:" at 288.125,-15.583 h1.14
  text "LAYOUT BY:" at 326.352,-15.583 h1.14
  text "or any information contained therein. TI and/or its licensors do not warrant that this design will meet" at 160.757,-18.237 h1.14
  text ".PRJ_Engineer" at 289.395,-19.52 h1.78
  text ".PCB_Layout" at 327.635,-19.52 h1.78
  text "the specifications, will be suitable for your application or fit for any particular purpose, or will operate in" at 160.757,-21.099 h1.14
  text ".Layer_Name" at 14.656,-21.806 h1.52
  text "ALTIUM DESIGNER VERSION:" at 326.352,-23.457 h1.14
  text "an implementation. TI and/or its licensors do not warrant that the design is production worthy. You should" at 160.757,-23.961 h1.14
  text "completely validate and test your design implementation to confirm the system functionality for your application." at 161.9,-26.822 h1.14
  text ".print_Scale" at 289.395,-26.843 h1.78
  text ".Application_BuildNumber" at 327.635,-26.843 h1.78
  text "1" at 18.792,-32.093 h1.78
  text "2" at 82.182,-32.093 h1.78
  text "3" at 145.411,-32.093 h1.78
  text "4" at 209.08,-32.093 h1.78
  text "5" at 272.555,-32.093 h1.78
  text "6" at 336.182,-32.093 h1.78
M10 Fab Notes:
  drawing of 189 lines, arcs and shapes, not listed
  text "DESIGN INFORMATION" at 314.503,161.447 h1.52
  text "MIN. TRACK WIDTH:" at 298.131,158.091 h1.52
  text "8" at 325.976,158.091 h1.52
  text "MIL" at 329.907,158.091 h1.52
  text "MIN. CLEARANCE:" at 298.131,154.938 h1.52
  text "0.2" at 324.452,154.938 h1.52
  text "mm" at 329.907,154.938 h1.52
  text "MIN. VIA PAD SIZE:" at 298.131,151.785 h1.52
  text "24" at 325.214,151.785 h1.52
  text "MIL" at 329.907,151.785 h1.52
  text "0.05mm (2MIL)" at 315.784,148.486 h1.52
  text "MINIMUM ANNULAR RING" at 289.769,148.277 h1.52
  text "EXTERNAL" at 333.768,148.277 h1.52
  text "PER" at 294.849,145.48 h1.52
  text "IPC-D-275 CLASS 2 LEVEL C" at 300.437,145.48 h1.52
  text "MIL, HOLES" at 338.238,142.928 h1.52
  text "+/-" at 328.27,142.709 h1.52
  text "+/-" at 349.961,142.709 h1.52
  text "REGISTRATION TOLERANCES:" at 289.769,142.682 h1.52
  text "METAL" at 320.243,142.682 h1.52
  text "5" at 334.879,142.683 h1.52
  text "3" at 356.037,142.683 h1.52
  text "MIL" at 358.99,142.682 h1.52
  text "HOLE SIZE TOLERANCE (UNLESS OTHERWISE SPECIFIED):" at 289.769,140.185 h1.52
  text "+/-" at 349.961,140.112 h1.52
  text "3" at 356.037,140.085 h1.52
  text "MIL" at 358.99,140.085 h1.52
  text "MATERIAL:" at 287.87,136.589 h1.52
  text "FR-4 High Tg" at 312.926,133.324 h1.52
  text "X" at 309.257,133.122 h1.52
  text "FR-408" at 298.563,133.007 h1.52
  text "OTHER" at 336.358,133.007 h1.52
  text "62 MIL (1.6mm) +/-10%" at 306.694,129.374 h1.52
  text "X" at 303.643,129.312 h1.52
  text "THICKNESS:" at 289.769,129.165 h1.52
  text "OTHER" at 339.33,129.165 h1.52
  text "TOLERANCE:" at 289.769,125.652 h1.52
  text "X" at 311.314,125.652 h1.52
  text "ANSI IPC-6012 TYPE 3 CLASS 2" at 315.836,125.652 h1.52
  text "OTHER +/-" at 315.835,121.989 h1.52
  text "BOW & TWIST:" at 289.769,118.302 h1.52
  text "X" at 311.314,118.302 h1.52
  text "ANSI IPC-6012 TYPE 3 CLASS 2" at 315.836,118.302 h1.52
  text "OTHER +/-" at 315.835,114.576 h1.52
  text "DRILLING:" at 287.87,111.258 h1.52
  text "NC_DRILL FILES" at 332.599,108.586 h1.52
  text "REFERENCE:" at 289.769,108.486 h1.52
  text "X" at 306.463,108.484 h1.52
  text "AS SHOWN" at 310.984,108.486 h1.52
  text "X" at 329.348,108.486 h1.52
  text "OTHER" at 340.168,104.873 h1.52
  text "PTH COPPER THICKNESS:" at 289.761,104.783 h1.52
  text "X" at 318.697,104.783 h1.52
  text "20-30 um" at 321.948,104.783 h1.52
  text "BOARD FINISH:" at 287.87,101.034 h1.52
  text "SILKSCREEN:" at 291.812,98.237 h1.52
  text "X" at 316.14,98.237 h1.52
  text "TOP" at 319.112,98.237 h1.52
  text "X" at 329.094,98.237 h1.52
  text "BOTTOM" at 332.091,98.237 h1.52
  text "SILKSCREEN COLOR:" at 291.812,94.295 h1.52
  text "X" at 316.115,94.295 h1.52
  text "WHITE" at 319.112,94.295 h1.52
  text "OTHER" at 332.091,94.295 h1.52
  text "X" at 319.442,90.652 h1.52
  text "GREEN" at 322.439,90.652 h1.52
  text "OTHER" at 338.136,90.652 h1.52
  text "SOLDER RESIST COLOR:" at 291.812,90.477 h1.52
  text "X" at 319.442,86.734 h1.52
  text "MATTE" at 322.439,86.734 h1.52
  text "SEMI-GLOSS" at 338.125,86.717 h1.52
  text "IMMERSION GOLD (ENIG)" at 314.819,82.345 h1.52
  text "ENEPIG" at 348.793,82.162 h1.52
  text "SURFACE FINISH:" at 287.87,82.136 h1.52
  text "X" at 310.298,82.136 h1.52
  text "IMM. TIN/SILVER OR EQUIV" at 296.24,78.649 h1.52
  text "OTHER" at 332.599,78.549 h1.52
  text "ARRAY/PANEL:" at 287.87,74.602 h1.52
  text "CUT AND TRIM PER M1 BOARD OUTLINE" at 314.819,74.393 h1.52
  text "N.C. ROUTE" at 314.819,70.94 h1.52
  text "X" at 332.295,70.94 h1.52
  text "V. SCORE" at 336.816,70.94 h1.52
  text "CERTIFICATION:" at 287.87,67.66 h1.52
  text "MATERIALS AND WORKMANSHIP FOR ALL PCBS" at 306.285,67.66 h1.52
  text "TO MEET OR EXCEED THE REQUIREMENTS OF:" at 306.285,65.271 h1.52
  text "X" at 297.078,62.003 h1.52
  text "ANSI IPC-A-600F CLASS ->" at 300.329,62.003 h1.52
  text "X" at 342.188,62.003 h1.52
  text "2" at 344.982,62.003 h1.52
  text "1" at 336.981,61.965 h1.52
  text "3" at 353.973,61.965 h1.52
  text "X" at 317.702,58.252 h1.52
  text "RoHS" at 320.953,58.252 h1.52
  text "OTHER" at 337.321,58.252 h1.52
  text "PER ORDER" at 347.407,58.252 h1.52
  text "ALL BOARDS MUST MEET OR EXCEED UL94-V0 REQUIREMENTS." at 288.569,54.345 h1.52
  text "PCB MUST BEAR THE UL94V-0 UL REGISTERED MATERIAL ID NUMBER" at 288.569,51.397 h1.52
  text "ADDITIONAL REQUIREMENTS:" at 287.87,47.094 h1.52
  text "MICROSECTION:" at 289.769,44.373 h1.52
  text "YES" at 312.775,44.373 h1.52
  text "REQUIRED" at 334.657,40.707 h1.52
  text "BARE BOARD ELEC. TEST:" at 289.769,40.634 h1.52
  text "NONE" at 322.935,40.634 h1.52
  text "X" at 331.66,40.634 h1.52
  text "PER ORDER" at 349.693,40.634 h1.52
  text "XX MIL VIAS REQUIRE NON-CONDUCTIVE FILL AND PLANARIZE" at 294.04,35.428 h1.5
  text "XX MIL VIAS REQUIRE CONDUCTIVE FILL AND PLANARIZE" at 294.243,32.787 h1.52
  text "OUTER XX MIL TRACES REQUIRE 50 OHM SINGLE-ENDED IMPEDANCE" at 294.218,28.637 h1.47
  text "LAYER 2 & 3 (INNER LAYERS) XX MIL WIDE, XX MIL SPACE / TRACES REQUIRE 100 OHM DIFFERENTIAL IMPEDANCE" at 294.015,22.65 h1.52
  text ".Layer_Name" at 14.656,-21.806 h1.52
M11 Gerber Information:
  lines w0.254: -7.417,-23.626 160.223,-23.626 ; -7.417,-18.462 160.274,-18.462 ; -7.417,-13.297 -7.417,-28.791 94.31,-28.791 160.274,-28.791 160.274,-13.297 -7.404,-13.297 -7.404,-28.791 32.614,-28.791 ; 55.194,-28.791 55.194,-13.297 ; 87.376,-18.462 87.376,-13.297 ; 108.712,-18.462 108.712,-13.297 ; 124.511,-28.956 124.511,-23.804
  text "ALL ARTWORK VIEWED FROM TOP SIDE" at -5.804,-16.654 h1.52
  text "BOARD #:" at 57.099,-16.654 h1.52
  text ".PRJ_Number" at 70.955,-16.654 h1.52
  text "REV:" at 92.405,-16.654 h1.52
  text ".PCB_Rev" at 99.809,-16.654 h1.52
  text "SVN REV:" at 113.69,-16.654 h1.52
  text ".VersionControl_RevNumber" at 126.543,-16.654 h1.52
  text "LAYER NAME =" at -5.804,-21.806 h1.52
  text "TID #:" at 57.099,-21.819 h1.52
  text ".TID" at 70.955,-21.819 h1.52
  text "PLOT NAME =" at -5.804,-27.034 h1.52
  text ".plot_File_Name" at 14.656,-27.034 h1.52
  text "GENERATED    :" at 57.15,-27.034 h1.52
  text ".Print_Date" at 79.235,-27.034 h1.52
  text ".Print_Time" at 97.752,-27.034 h1.52
  text "TEXAS INSTRUMENTS" at 129.87,-27.034 h1.52
M12 Stackup:
  drawing of 191 lines, arcs and shapes, not listed
  text "Layer" at 248.865,196.024 h1.52
  text "Name" at 259.277,196.024 h1.52
  text "Material" at 282.892,196.024 h1.52
  text "Thickness" at 304.731,196.024 h1.52
  text "Constant" at 321.236,196.024 h1.52
  text "Board Layer Stack" at 335.711,196.024 h1.52
  text "1" at 248.865,192.976 h1.52
  text "Top Overlay" at 259.277,192.976 h1.52
  text "2" at 248.865,189.928 h1.52
  text "Top Solder" at 259.277,189.928 h1.52
  text "Solder Resist" at 282.892,189.928 h1.52
  text "0.40mil" at 304.731,189.928 h1.52
  text "3.5" at 321.236,189.928 h1.52
  text "3" at 248.865,186.88 h1.52
  text "Top Layer" at 259.277,186.88 h1.52
  text "Copper" at 282.892,186.88 h1.52
  text "1.40mil" at 304.731,186.88 h1.52
  text "4" at 248.865,183.832 h1.52
  text "Dielectric1" at 259.277,183.832 h1.52
  text "FR-4" at 282.892,183.832 h1.52
  text "59.20mil" at 304.731,183.832 h1.52
  text "4.8" at 321.236,183.832 h1.52
  text "5" at 248.865,180.784 h1.52
  text "Bottom Layer" at 259.277,180.784 h1.52
  text "Copper" at 282.892,180.784 h1.52
  text "1.40mil" at 304.731,180.784 h1.52
  text "6" at 248.865,177.737 h1.52
  text "Bottom Solder" at 259.277,177.737 h1.52
  text "Solder Resist" at 282.892,177.737 h1.52
  text "0.40mil" at 304.731,177.737 h1.52
  text "3.5" at 321.236,177.737 h1.52
  text "7" at 248.865,174.689 h1.52
  text "Bottom Overlay" at 259.277,174.689 h1.52
  text ".Layer_Name" at 14.656,-21.806 h1.52
M13 Component Bodies Top:
  text ".Layer_Name" at 14.656,-21.806 h1.52
M14 Component Bodies Bottom:
  text ".Layer_Name" at 14.656,-21.806 h1.52
M15 Courtyards Top:
  text ".Layer_Name" at 14.656,-21.806 h1.52
M16 Courtyards Bottom:
  text ".Layer_Name" at 14.656,-21.806 h1.52
Drill Drawing:
  text ".Layer_Name" at 14.656,-21.806 h1.52
Mechanical 17:
  text ".Layer_Name" at 14.656,-21.806 h1.52
Mechanical 18:
  text ".Layer_Name" at 14.656,-21.806 h1.52
Mechanical 19:
  text ".Layer_Name" at 14.656,-21.806 h1.52

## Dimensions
0,0 to 0,25.7 on M2 Board Dimensions
0,0 to 36.5,0 on M2 Board Dimensions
